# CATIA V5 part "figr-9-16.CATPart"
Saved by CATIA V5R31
Part number: Part1
Bounding box of the stored display mesh (mm): x -77.304 to 77.304, y -77.304 to 125.507, z 0 to 125
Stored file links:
  D:\PROJECTS\Project 2021\US EDITION\CATIA V5 6R 2021\Resources\Part Files\c09_catia_v5_6r2021_prt\c09_catia_v5_6r2021_prt\figr-9-16.CATPart
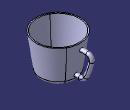
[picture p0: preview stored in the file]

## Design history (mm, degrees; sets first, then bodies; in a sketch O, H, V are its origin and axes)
Set1
  Plane1: type Normal, Curve Sketch3, RefPoint vertex of Sketch3
Body1 (main body)
  Sketch1 on yz-plane, origin (0, 0, 0), H (0, 1, 0), V (0, 0, 1)
    line L1 (0, 0) -> (60, 0)
    point P1 (60, 0)
    point P2 (60, 0)
    line L2 (60, 0) -> (77.5, 125)
    point P3 (77.5, 125)
    line L3 (77.5, 125) -> (0, 125)
    point P4 (0, 125)
    line L4 (0, 125) -> (0, 0)
    axis line L5 (0, 150.2858) -> (0, -31.0593)
    point P5 (0, 150.2858)
    radius about axis P1 L5 = 60
    radius about axis P3 L5 = 77.5
    distance L3 L1 = 125
    horizontal: L1 H, L3 H
    coincidence: P4 V, P2 P1, P5 V
    vertical: L4 V, L5 V
  Shaft1: profile Sketch1, axis Sketch1.L5, angle 360
  Fillet1: radius 15, on edge [face of Shaft1 | face of Shaft1]
  Shell1: ExtOffset 0, Face face of Shaft1, IntOffset 4
  Sketch2 on Plane1, origin (0, 62.9841, 0), H (-1, 0, 0), V (0, 0, 1)
    circle A1 centre (0, 22.002) radius 7.5
    reference projected point E1 (0, 22.002) from vertex of Sketch3
    radius A1 = 7.5
    concentricity: A1 E1
  Sketch3 on yz-plane, origin (0, 0, 0), H (0, 1, 0), V (0, 0, 1)
    line L1 (62.9841, 22.002) -> (78.2172, 22.002)
    arc A1 centre (78.2172, 44.1133) radius 22.1113 from (78.2172, 22.002) to (97.9307, 34.0988) ccw
    arc A2 centre (-112.3295, 140.9107) radius 235.8349 from (97.9307, 34.0988) to (117.8681, 89.6549) ccw
    arc A3 centre (104.0328, 92.7355) radius 14.1742 from (117.8681, 89.6549) to (104.4272, 106.9041) ccw
    arc A4 centre (93.6744, -279.4123) radius 386.4661 from (104.4272, 106.9041) to (82.9216, 106.9041) ccw
    horizontal: L1 H
    tangency: A1 L1, A2 A1, A3 A2, A4 A3
  Rib1: profile Sketch2, centre curve Sketch3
